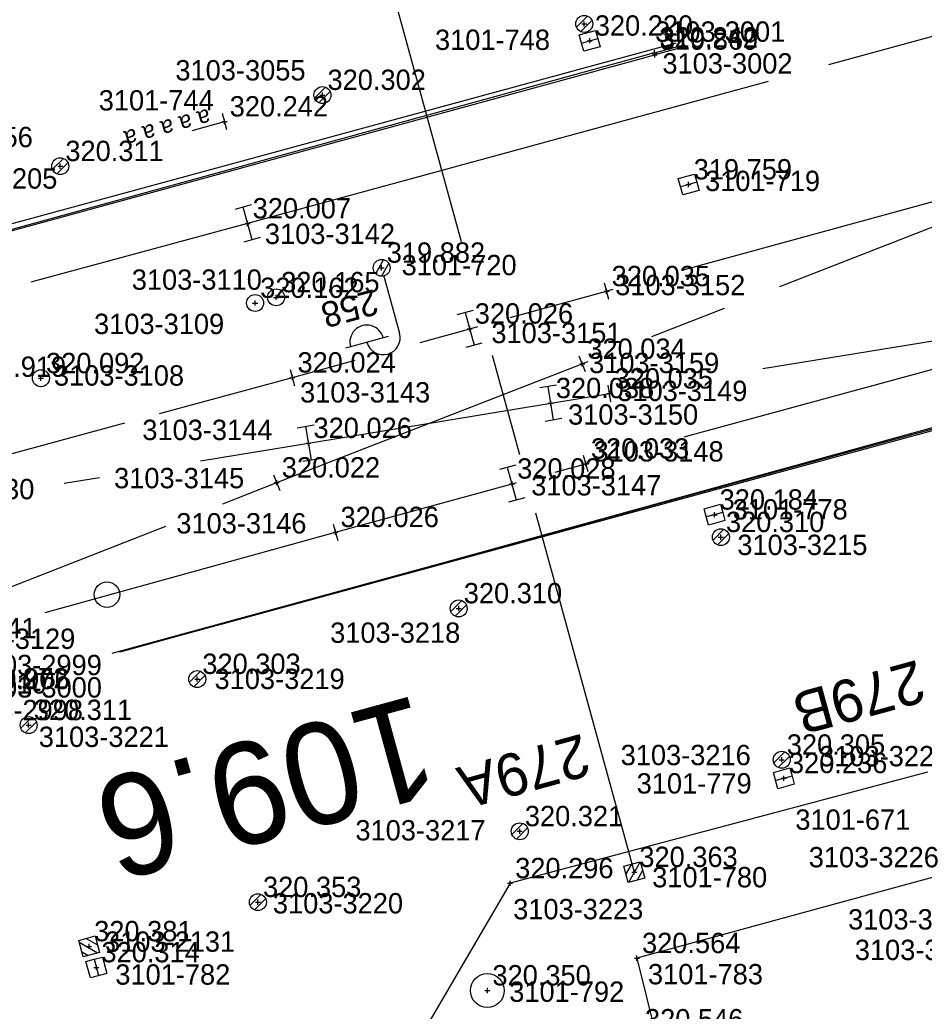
# Model space of a CAD drawing. Extents: x -821875 to -821475, y -1070280 to -1069975.
# Drawn here: x -821648.14 to -821621.48, y -1070237.36 to -1070208.12 of the extents above; entities that cross this region are included whole.
import ezdxf

# ---------------------------------------------------------------- set-up
doc = ezdxf.new("R2010")
doc.units = 0
for name, color, linetype in [('Vrstva 1', 7, 'Continuous'), ('Vrstva 11', 7, 'Continuous'), ('Vrstva 14', 7, 'Continuous'), ('Vrstva 17', 7, 'Continuous'), ('Vrstva 2', 7, 'Continuous'), ('Vrstva 23', 7, 'Continuous'), ('Vrstva 25', 7, 'Continuous'), ('Vrstva 28', 7, 'Continuous'), ('Vrstva 3', 7, 'Continuous'), ('Vrstva 36', 7, 'Continuous'), ('Vrstva 43', 7, 'Continuous'), ('Vrstva 6', 7, 'Continuous'), ('Vrstva 60', 7, 'Continuous'), ('Vrstva 61', 7, 'Continuous'), ('Vrstva 7', 7, 'Continuous')]:
    doc.layers.add(name, color=color, linetype=linetype)

# ---------------------------------------------------------------- blocks, each defined once
blk = doc.blocks.new('BOD')
at = {"layer": 'Vrstva 3'}
for p, q in [((-0.15, 0), (0.15, 0)), ((0, -0.15), (0, 0.15))]:
    blk.add_line(p, q, dxfattribs=at)

msp = doc.modelspace()

# ---------------------------------------------------------------- linework, layer by layer
at = {"layer": 'Vrstva 1'}
for points in [[(-821591.155, -1070200.399), (-821624.302, -1070209.451)], [(-821626.08, -1070209.937), (-821641.428, -1070214.128)], [(-821641.428, -1070214.128), (-821647.816, -1070215.859)], [(-821633.687, -1070216.904), (-821630.842, -1070216.127)], [(-821636.339, -1070217.633), (-821634.879, -1070217.23), (-821634.635, -1070217.163)], [(-821640.107, -1070218.673), (-821638.252, -1070218.161)], [(-821640.569, -1070221.768), (-821631.559, -1070218.269)], [(-821639.634, -1070220.603), (-821632.488, -1070219.428), (-821630.755, -1070219.144)], [(-821632.358, -1070221.456), (-821631.454, -1070221.211)], [(-821638.838, -1070223.23), (-821633.628, -1070221.801), (-821633.5, -1070221.766)]]:
    msp.add_lwpolyline(points, dxfattribs=at)
at = {"layer": 'Vrstva 11'}
for p, q in [((-821637.848, -1070204.77), (-821635.133, -1070214.658)), ((-821634.211, -1070218.014), (-821633.407, -1070220.943)), ((-821632.934, -1070222.664), (-821630.026, -1070233.254)), ((-821630.105, -1070233.017), (-821630.27, -1070233.307)), ((-821629.851, -1070232.949), (-821630.199, -1070233.561)), ((-821629.781, -1070233.204), (-821629.944, -1070233.491))]:
    msp.add_line(p, q, dxfattribs=at)
msp.add_lwpolyline([(-821629.719, -1070233.429), (-821630.201, -1070233.561), (-821630.333, -1070233.079), (-821629.851, -1070232.947)], close=True, dxfattribs=at)
msp.add_lwpolyline([(-821629.719, -1070233.429), (-821630.201, -1070233.561), (-821630.333, -1070233.079), (-821629.851, -1070232.947), (-821629.719, -1070233.429)], dxfattribs=at)
at = {"layer": 'Vrstva 14'}
for p, q in [((-821652.05, -1070215.131), (-821628.792, -1070208.803)), ((-821603.365, -1070215.368), (-821645.213, -1070226.773))]:
    msp.add_line(p, q, dxfattribs=at)
for points in [[(-821629.431, -1070209.09), (-821628.527, -1070208.845)], [(-821629.431, -1070209.09), (-821651.425, -1070215.14)], [(-821651.275, -1070215.126), (-821629.423, -1070209.153)], [(-821628.557, -1070208.918), (-821629.423, -1070209.153)], [(-821613.18, -1070217.993), (-821645.432, -1070226.806)], [(-821645.149, -1070226.747), (-821613.257, -1070217.946)]]:
    msp.add_lwpolyline(points, dxfattribs=at)
at = {"layer": 'Vrstva 17'}
for p, q in [((-821621.383, -1070230.309), (-821633.688, -1070233.585)), ((-821633.688, -1070233.585), (-821637.314, -1070239.784))]:
    msp.add_line(p, q, dxfattribs=at)
at = {"layer": 'Vrstva 2'}
for p, q in [((-821630.776, -1070216.368), (-821630.908, -1070215.886)), ((-821631.468, -1070218.502), (-821631.65, -1070218.036)), ((-821640.173, -1070218.431), (-821640.041, -1070218.915)), ((-821630.715, -1070219.391), (-821630.795, -1070218.897)), ((-821631.389, -1070221.452), (-821631.519, -1070220.97)), ((-821640.66, -1070221.535), (-821640.478, -1070222.001)), ((-821638.905, -1070222.989), (-821638.771, -1070223.471))]:
    msp.add_line(p, q, dxfattribs=at)
for points in [[(-821605.28, -1070209.135), (-821607.281, -1070209.67), (-821628.619, -1070215.518)], [(-821614.838, -1070211.741), (-821625.745, -1070215.999)], [(-821630.657, -1070216.076), (-821630.842, -1070216.127)], [(-821613.652, -1070216.37), (-821626.237, -1070218.411)], [(-821627.379, -1070216.637), (-821629.521, -1070217.473)], [(-821618.237, -1070217.617), (-821628.568, -1070220.426)], [(-821631.399, -1070218.206), (-821631.559, -1070218.269)], [(-821644.029, -1070219.734), (-821640.107, -1070218.673)], [(-821630.721, -1070219.139), (-821630.755, -1070219.144)], [(-821650.582, -1070221.506), (-821645.043, -1070220.008)], [(-821642.816, -1070221.127), (-821639.634, -1070220.603)], [(-821631.438, -1070221.207), (-821631.454, -1070221.211)], [(-821646.835, -1070221.788), (-821645.795, -1070221.617)], [(-821642.158, -1070222.39), (-821640.569, -1070221.768)], [(-821657.296, -1070228.321), (-821643.839, -1070223.049)], [(-821647.397, -1070225.594), (-821638.838, -1070223.23)]]:
    msp.add_lwpolyline(points, dxfattribs=at)
at = {"layer": 'Vrstva 23'}
msp.add_lwpolyline([(-821618.032, -1070237.847), (-821619.404, -1070232.915), (-821629.947, -1070235.793), (-821628.796, -1070240.434), (-821629.722, -1070241.929), (-821630.734, -1070242.226), (-821629.687, -1070246.101), (-821630.928, -1070246.466), (-821632.123, -1070248.555), (-821635.379, -1070249.449), (-821635.229, -1070250)], dxfattribs=at)
at = {"layer": 'Vrstva 25'}
for p, q in [((-821637.416, -1070215.192), (-821637.654, -1070215.609)), ((-821637.262, -1070215.301), (-821637.481, -1070215.684)), ((-821637.408, -1070215.676), (-821636.946, -1070217.364)), ((-821637.283, -1070217.457), (-821638.538, -1070217.8))]:
    msp.add_line(p, q, dxfattribs=at)
msp.add_circle((-821637.474, -1070215.435), 0.25, dxfattribs=at)
msp.add_circle((-821637.474, -1070215.435), 0.25, dxfattribs=at)
for centre, start, end in [((-821637.912, -1070217.622), 14.6024, 196.0075), ((-821637.428, -1070217.496), 195.3049, 15.3049)]:
    msp.add_arc(centre, 0.5, start, end, dxfattribs=at)
at = {"layer": 'Vrstva 28'}
for p, q in [((-821640.611, -1070216.305), (-821640.561, -1070216.305)), ((-821641.23, -1070216.472), (-821641.18, -1070216.472)), ((-821647.545, -1070218.692), (-821647.495, -1070218.692))]:
    msp.add_line(p, q, dxfattribs=at)
for centre in [(-821640.586, -1070216.305), (-821641.205, -1070216.472), (-821647.52, -1070218.692)]:
    msp.add_circle(centre, 0.25, dxfattribs=at)
at = {"layer": 'Vrstva 3'}
for p, q in [((-821641.318, -1070213.58), (-821641.8, -1070213.711)), ((-821641.297, -1070214.61), (-821641.559, -1070213.646)), ((-821641.056, -1070214.545), (-821641.538, -1070214.676)), ((-821635.252, -1070216.814), (-821634.771, -1070216.682)), ((-821635.011, -1070216.748), (-821634.747, -1070217.712)), ((-821634.987, -1070217.778), (-821634.506, -1070217.646)), ((-821632.321, -1070218.894), (-821632.815, -1070218.974)), ((-821632.408, -1070219.922), (-821632.568, -1070218.934)), ((-821632.161, -1070219.882), (-821632.655, -1070219.962)), ((-821639.962, -1070220.15), (-821639.469, -1070220.069)), ((-821639.715, -1070220.11), (-821639.553, -1070221.096)), ((-821639.799, -1070221.137), (-821639.306, -1070221.056)), ((-821633.518, -1070221.253), (-821634, -1070221.384)), ((-821633.497, -1070222.283), (-821633.759, -1070221.319)), ((-821633.256, -1070222.218), (-821633.738, -1070222.349))]:
    msp.add_line(p, q, dxfattribs=at)
at = {"layer": 'Vrstva 36'}
for p, q in [((-821631.73, -1070208.334), (-821631.408, -1070208.011)), ((-821631.6, -1070208.469), (-821631.273, -1070208.142)), ((-821639.452, -1070210.431), (-821639.128, -1070210.108)), ((-821639.322, -1070210.566), (-821638.994, -1070210.238)), ((-821647.182, -1070212.529), (-821646.858, -1070212.206)), ((-821647.052, -1070212.664), (-821646.724, -1070212.336)), ((-821627.702, -1070223.469), (-821627.38, -1070223.146)), ((-821627.572, -1070223.604), (-821627.245, -1070223.276)), ((-821635.434, -1070225.569), (-821635.11, -1070225.246)), ((-821635.304, -1070225.704), (-821634.976, -1070225.376)), ((-821643.142, -1070227.653), (-821642.82, -1070227.33)), ((-821643.012, -1070227.788), (-821642.685, -1070227.46)), ((-821648.114, -1070229.011), (-821647.79, -1070228.688)), ((-821647.984, -1070229.146), (-821647.656, -1070228.818)), ((-821625.908, -1070230.034), (-821625.586, -1070229.711)), ((-821625.778, -1070230.169), (-821625.451, -1070229.842)), ((-821633.632, -1070232.143), (-821633.31, -1070231.82)), ((-821633.502, -1070232.278), (-821633.175, -1070231.95)), ((-821641.354, -1070234.232), (-821641.03, -1070233.909)), ((-821641.224, -1070234.367), (-821640.896, -1070234.04)), ((-821646.393, -1070235.323), (-821645.851, -1070235.635)), ((-821646.19, -1070235.209), (-821645.855, -1070235.403)), ((-821646.32, -1070235.595), (-821646.124, -1070235.709))]:
    msp.add_line(p, q, dxfattribs=at)
msp.add_lwpolyline([(-821645.925, -1070235.138), (-821645.796, -1070235.621), (-821646.279, -1070235.75), (-821646.408, -1070235.267), (-821645.925, -1070235.138)], dxfattribs=at)
for centre in [(-821631.5, -1070208.242), (-821639.221, -1070210.339), (-821646.951, -1070212.437), (-821627.472, -1070223.377), (-821635.203, -1070225.477), (-821642.912, -1070227.561), (-821647.883, -1070228.919), (-821625.678, -1070229.942), (-821633.402, -1070232.051), (-821641.123, -1070234.14)]:
    msp.add_circle(centre, 0.25, dxfattribs=at)
at = {"layer": 'Vrstva 43'}
for points in [[(-821631.58, -1070208.805), (-821631.646, -1070208.564), (-821631.164, -1070208.432), (-821631.032, -1070208.914), (-821631.514, -1070209.046), (-821631.58, -1070208.805), (-821631.098, -1070208.673)], [(-821628.182, -1070212.911), (-821628.116, -1070213.153), (-821628.598, -1070213.285), (-821628.73, -1070212.803), (-821628.248, -1070212.671), (-821628.182, -1070212.911), (-821628.664, -1070213.045)], [(-821627.418, -1070222.649), (-821627.352, -1070222.89), (-821627.834, -1070223.022), (-821627.966, -1070222.54), (-821627.484, -1070222.408), (-821627.418, -1070222.649), (-821627.9, -1070222.781)], [(-821625.374, -1070230.421), (-821625.308, -1070230.662), (-821625.79, -1070230.794), (-821625.922, -1070230.312), (-821625.44, -1070230.18), (-821625.374, -1070230.421), (-821625.856, -1070230.553)], [(-821645.951, -1070235.823), (-821645.71, -1070235.758), (-821645.581, -1070236.241), (-821646.064, -1070236.37), (-821646.193, -1070235.887), (-821645.951, -1070235.823), (-821645.823, -1070236.305)]]:
    msp.add_lwpolyline(points, dxfattribs=at)
msp.add_circle((-821634.358, -1070236.746), 0.5, dxfattribs=at)
at = {"layer": 'Vrstva 6'}
for p, q in [((-821642.04, -1070211.363), (-821642.17, -1070210.881)), ((-821643.061, -1070211.38), (-821642.105, -1070211.122))]:
    msp.add_line(p, q, dxfattribs=at)
at = {"layer": 'Vrstva 7'}
msp.add_circle((-821645.574, -1070225.072), 0.375, dxfattribs=at)

# ---------------------------------------------------------------- block references
at = {"layer": 'Vrstva 60', "xscale": 0.5, "yscale": 0.5}
for p in [(-821631.5, -1070208.242), (-821631.339, -1070208.739), (-821629.431, -1070209.09), (-821629.423, -1070209.153), (-821639.221, -1070210.339), (-821642.105, -1070211.122), (-821646.951, -1070212.437), (-821628.423, -1070212.978), (-821641.428, -1070214.128), (-821637.474, -1070215.435), (-821630.842, -1070216.127), (-821641.205, -1070216.472), (-821640.586, -1070216.305), (-821634.879, -1070217.23), (-821631.559, -1070218.269), (-821647.52, -1070218.692), (-821640.107, -1070218.673), (-821630.755, -1070219.144), (-821632.488, -1070219.428), (-821639.634, -1070220.603), (-821631.454, -1070221.211), (-821640.569, -1070221.768), (-821633.628, -1070221.801), (-821627.659, -1070222.715), (-821638.838, -1070223.23), (-821627.472, -1070223.377), (-821635.203, -1070225.477), (-821642.912, -1070227.561), (-821647.883, -1070228.919), (-821625.678, -1070229.942), (-821625.615, -1070230.487), (-821633.402, -1070232.051), (-821630.026, -1070233.254), (-821633.688, -1070233.585), (-821641.123, -1070234.14), (-821646.102, -1070235.444), (-821629.947, -1070235.793), (-821645.887, -1070236.064), (-821634.358, -1070236.746)]:
    msp.add_blockref('BOD', p, dxfattribs=at)

# ---------------------------------------------------------------- texts
at = {"layer": 'Vrstva 11'}
for s, p in [('279B', (-821621.675, -1070226.988)), ('279A', (-821631.557, -1070229.163))]:
    msp.add_text(s, height=1.25, rotation=195.3174, dxfattribs=at).set_placement(p)
at = {"layer": 'Vrstva 25'}
msp.add_text('258', height=0.75, rotation=195.3049, dxfattribs=at).set_placement((-821637.706, -1070216.057))
at = {"layer": 'Vrstva 6'}
msp.add_text('  a a a a a', height=0.5, rotation=195.1172, dxfattribs=at).set_placement((-821642.235, -1070210.639))
at = {"layer": 'Vrstva 60'}
for s, p in [('3103-3001', (-821629.41, -1070208.768)), ('3101-748', (-821635.901, -1070209.009)), ('3103-3002', (-821629.196, -1070209.706)), ('3103-3055', (-821643.556, -1070209.909)), ('3101-744', (-821645.817, -1070210.795)), ('3103-3056', (-821651.597, -1070211.877)), ('3101-719', (-821627.938, -1070213.171)), ('3103-3142', (-821640.917, -1070214.732)), ('3101-720', (-821636.886, -1070215.653)), ('3103-3110', (-821644.843, -1070216.082)), ('3103-3152', (-821630.589, -1070216.243)), ('3103-3109', (-821645.955, -1070217.388)), ('3103-3151', (-821634.239, -1070217.655)), ('3103-3159', (-821631.358, -1070218.539)), ('3103-3108', (-821647.137, -1070218.909)), ('3103-3143', (-821639.88, -1070219.406)), ('3103-3149', (-821630.527, -1070219.363)), ('3103-3150', (-821631.978, -1070220.059)), ('3103-3144', (-821644.532, -1070220.513)), ('3103-3148', (-821631.227, -1070221.147)), ('3103-3145', (-821645.364, -1070221.935)), ('3103-3130', (-821651.552, -1070222.259)), ('3103-3147', (-821633.066, -1070222.148)), ('3101-778', (-821627.123, -1070222.856)), ('3103-3146', (-821643.529, -1070223.268)), ('3103-3215', (-821626.987, -1070223.904)), ('3103-3129', (-821650.344, -1070226.673)), ('3103-3218', (-821638.993, -1070226.493)), ('3103-2999', (-821649.562, -1070227.446)), ('3103-3219', (-821642.402, -1070227.856)), ('3103-3000', (-821649.559, -1070228.107)), ('3103-2998', (-821650.117, -1070228.775)), ('3103-3221', (-821647.585, -1070229.564)), ('3103-3216', (-821630.427, -1070230.101)), ('3103-3224', (-821624.575, -1070230.134)), ('3101-779', (-821629.955, -1070230.937)), ('3101-671', (-821625.277, -1070232.006)), ('3103-3217', (-821638.248, -1070232.321)), ('3103-3226', (-821624.881, -1070233.113)), ('3101-780', (-821629.497, -1070233.704)), ('3103-3220', (-821640.681, -1070234.473)), ('3103-3223', (-821633.596, -1070234.646)), ('3103-3227', (-821623.722, -1070234.947)), ('3103-2131', (-821645.631, -1070235.603)), ('3103-3228', (-821623.523, -1070235.848)), ('3101-782', (-821645.328, -1070236.573)), ('3101-783', (-821629.622, -1070236.563)), ('3101-792', (-821633.712, -1070237.08))]:
    msp.add_text(s, height=0.6, dxfattribs=at).set_placement(p)
at = {"layer": 'Vrstva 61'}
for s, p in [('320.220', (-821631.189, -1070208.589)), ('320.242', (-821629.281, -1070208.94)), ('319.869', (-821629.273, -1070209.003)), ('320.302', (-821639.071, -1070210.189)), ('320.242', (-821641.955, -1070210.972)), ('320.311', (-821646.801, -1070212.287)), ('319.759', (-821628.273, -1070212.828)), ('320.205', (-821649.937, -1070213.1)), ('320.007', (-821641.278, -1070213.978)), ('319.882', (-821637.324, -1070215.285)), ('320.165', (-821640.436, -1070216.155)), ('320.035', (-821630.692, -1070215.977)), ('320.162', (-821641.055, -1070216.322)), ('320.026', (-821634.729, -1070217.08)), ('320.034', (-821631.409, -1070218.119)), ('320.024', (-821639.957, -1070218.523)), ('319.919', (-821649.678, -1070218.65)), ('320.092', (-821647.37, -1070218.542)), ('320.035', (-821630.605, -1070218.994)), ('320.038', (-821632.338, -1070219.278)), ('320.026', (-821639.484, -1070220.453)), ('320.033', (-821631.304, -1070221.061)), ('320.022', (-821640.419, -1070221.618)), ('320.028', (-821633.478, -1070221.651)), ('320.184', (-821627.509, -1070222.565)), ('320.026', (-821638.688, -1070223.08)), ('320.310', (-821627.322, -1070223.227)), ('320.310', (-821635.053, -1070225.327)), ('320.041', (-821650.55, -1070226.356)), ('320.303', (-821642.762, -1070227.411)), ('320.272', (-821649.613, -1070227.839)), ('319.906', (-821649.576, -1070227.86)), ('320.110', (-821650.252, -1070227.989)), ('320.311', (-821647.733, -1070228.769)), ('320.305', (-821625.528, -1070229.792)), ('320.236', (-821625.465, -1070230.337)), ('320.321', (-821633.252, -1070231.901)), ('320.363', (-821629.876, -1070233.104)), ('320.296', (-821633.538, -1070233.435)), ('320.353', (-821640.973, -1070233.99)), ('320.381', (-821645.952, -1070235.294)), ('320.564', (-821629.797, -1070235.643)), ('320.314', (-821645.737, -1070235.914)), ('320.350', (-821634.208, -1070236.596)), ('320.546', (-821629.709, -1070237.892))]:
    msp.add_text(s, height=0.6, dxfattribs=at).set_placement(p)
at = {"layer": 'Vrstva 7'}
msp.add_text('109.6', height=3, rotation=195.2753, dxfattribs=at).set_placement((-821636.414, -1070228.007))

doc.saveas('drawing.dxf')
